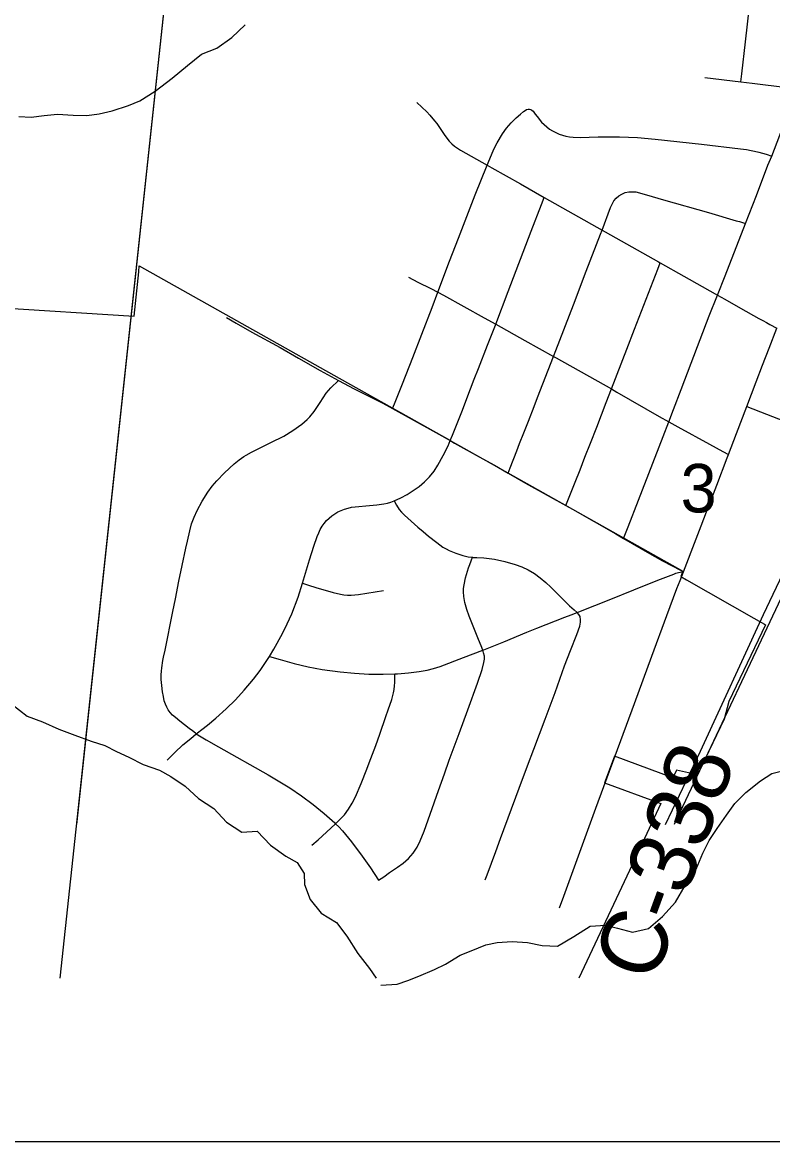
# Model space of a CAD drawing. Extents: x 0 to 34, y 0 to 22.
# Drawn here: x 7.77 to 8.418, y 17.5 to 18.466 of the extents above; entities that cross this region are included whole.
import ezdxf

# ---------------------------------------------------------------- set-up
doc = ezdxf.new("R2010")
doc.units = 0
for name, color, linetype in [('GM_X_City_Street', 7, 'Continuous'), ('GM_X_Corporation', 7, 'Continuous'), ('GM_X_County_Road', 7, 'Continuous'), ('GM_X_County_Road_Text', 7, 'Continuous'), ('GM_X_Minor_River', 7, 'Continuous'), ('GM_X_Rail_Line', 7, 'Continuous'), ('GM_X_Section_Text', 7, 'Continuous'), ('GM_X_Township_Road', 7, 'Continuous'), ('SH_Data', 7, 'Continuous')]:
    doc.layers.add(name, color=color, linetype=linetype)

msp = doc.modelspace()

# ---------------------------------------------------------------- linework, layer by layer
at = {"layer": 'GM_X_City_Street'}
for points in [[(8.39057, 18.41491), (8.39137, 18.42185), (8.39458, 18.44966), (8.39815, 18.48268)], [(8.35951, 18.41869), (8.39057, 18.41491), (8.40032, 18.41372), (8.43058, 18.41003), (8.44479, 18.4083), (8.46831, 18.40561), (8.49197, 18.4029), (8.49837, 18.40217)], [(8.28928, 18.02081), (8.29097, 18.02504), (8.29327, 18.03079), (8.30223, 18.05392), (8.32332, 18.1089), (8.32823, 18.1215), (8.33232, 18.13199), (8.33888, 18.14938), (8.34762, 18.17223), (8.36327, 18.21306), (8.37032, 18.23086), (8.37694, 18.2476), (8.39454, 18.29282), (8.40391, 18.31691), (8.41392, 18.34295), (8.41728, 18.35096), (8.42199, 18.36288), (8.42512, 18.37138), (8.42684, 18.37719), (8.42808, 18.3832), (8.42845, 18.38618), (8.42917, 18.39509), (8.43003, 18.4042), (8.43058, 18.41003)], [(8.08974, 18.13293), (8.09141, 18.13708), (8.09831, 18.15414), (8.10728, 18.17697), (8.11503, 18.19714), (8.12384, 18.2203), (8.12881, 18.23335), (8.13899, 18.26014), (8.14682, 18.27989), (8.16114, 18.31735), (8.17135, 18.34309), (8.17368, 18.34857), (8.17726, 18.35698), (8.18, 18.36239), (8.18466, 18.37017), (8.18824, 18.37504), (8.1922, 18.3796), (8.19649, 18.38389), (8.20019, 18.3872), (8.20274, 18.38927), (8.20424, 18.39032), (8.20555, 18.39105), (8.20683, 18.39136)], [(8.11083, 18.39703), (8.11929, 18.38897), (8.12202, 18.38621), (8.12599, 18.38142), (8.12786, 18.37893), (8.13477, 18.36853), (8.1387, 18.3637), (8.14091, 18.3615), (8.14329, 18.3595), (8.14847, 18.35603), (8.17135, 18.34309), (8.17561, 18.34068), (8.20011, 18.32698), (8.22077, 18.31527), (8.27069, 18.287), (8.27336, 18.28548), (8.31953, 18.25945), (8.32088, 18.2587), (8.34134, 18.24734), (8.36841, 18.23192), (8.37032, 18.23086), (8.37664, 18.22736), (8.39008, 18.21953), (8.40615, 18.21078), (8.40954, 18.20893), (8.41256, 18.20729), (8.41561, 18.20562), (8.42157, 18.20238)], [(8.20683, 18.39136), (8.20788, 18.39132), (8.20908, 18.39109), (8.21009, 18.39063), (8.21121, 18.38958), (8.21296, 18.38721), (8.21453, 18.38512), (8.2184, 18.3803), (8.22056, 18.37809), (8.2229, 18.37608), (8.22539, 18.37425), (8.22802, 18.37263), (8.23359, 18.36995), (8.2365, 18.3689), (8.23948, 18.36811), (8.24252, 18.36754), (8.24559, 18.36718), (8.25177, 18.36698), (8.26721, 18.36744), (8.28575, 18.36757), (8.30119, 18.36688), (8.31658, 18.36554), (8.35652, 18.36106), (8.39031, 18.35722), (8.39553, 18.35654), (8.39945, 18.35574), (8.40228, 18.35513), (8.40598, 18.35421), (8.41226, 18.35241), (8.41728, 18.35096)], [(8.13965, 18.10525), (8.14159, 18.11005), (8.1497, 18.13006), (8.15716, 18.15006), (8.16033, 18.15828), (8.16392, 18.16757), (8.17188, 18.18767), (8.17869, 18.20492), (8.17897, 18.20568), (8.18955, 18.23391), (8.20947, 18.28601), (8.21834, 18.30898), (8.22077, 18.31527)], [(8.18954, 18.07725), (8.19126, 18.08168), (8.19702, 18.09642), (8.19945, 18.10264), (8.20306, 18.1119), (8.20703, 18.12207), (8.21199, 18.13479), (8.21501, 18.14252), (8.22884, 18.17795), (8.23086, 18.18312), (8.24602, 18.22249), (8.25705, 18.2515), (8.26931, 18.28335), (8.27069, 18.287), (8.27808, 18.30659), (8.27934, 18.30942), (8.28083, 18.31214), (8.28277, 18.31454), (8.28515, 18.31653), (8.28781, 18.31814), (8.29068, 18.31932), (8.29371, 18.31996), (8.29681, 18.32016), (8.2999, 18.31988), (8.3089, 18.31747), (8.32381, 18.31317), (8.36264, 18.30208), (8.3865, 18.29512), (8.38948, 18.29427), (8.39454, 18.29282)], [(8.23942, 18.04914), (8.24123, 18.05363), (8.24753, 18.06927), (8.25164, 18.07987), (8.25592, 18.09089), (8.26059, 18.10295), (8.26603, 18.11696), (8.27427, 18.13823), (8.27875, 18.14983), (8.29196, 18.18405), (8.29854, 18.20139), (8.31876, 18.25324), (8.32088, 18.2587)], [(8.10356, 18.24647), (8.11163, 18.24198), (8.12269, 18.23645), (8.12881, 18.23335), (8.13371, 18.23086), (8.16886, 18.21132), (8.17897, 18.20568), (8.20406, 18.19169), (8.22884, 18.17795), (8.23115, 18.17666), (8.27875, 18.14983), (8.28342, 18.14719), (8.32004, 18.12612), (8.32823, 18.1215), (8.33619, 18.11701), (8.36348, 18.10209), (8.37503, 18.09577), (8.37976, 18.09319)]]:
    msp.add_lwpolyline(points, dxfattribs=at)
at = {"layer": 'GM_X_Corporation'}
for points in [[(6.81318, 17.77385), (6.90013, 18.71944), (7.91015, 18.64382), (7.81673, 17.77385)], [(8.81833, 17.64118), (8.84939, 17.97112), (8.84939, 18.54746), (7.91015, 18.64382), (7.80248, 17.64118)], [(7.74797, 18.22005), (7.86663, 18.21267), (7.87056, 18.25102), (7.87108, 18.25615), (8.04362, 18.15925), (8.08951, 18.13346), (8.13931, 18.1055), (8.1394, 18.10545), (8.16764, 18.0896), (8.18921, 18.07748), (8.34034, 17.99261), (8.33858, 17.98797), (8.34357, 17.98511), (8.4018, 17.95187), (8.41079, 17.94674), (8.41178, 17.94617), (8.39899, 17.91956), (8.38005, 17.87994), (8.37618, 17.86473), (8.35298, 17.81663), (8.33506, 17.82084), (8.33191, 17.81415), (8.28131, 17.83285), (8.27283, 17.80973), (8.32132, 17.79181), (8.30122, 17.74887), (8.26665, 17.67548), (8.25055, 17.64118)]]:
    msp.add_lwpolyline(points, dxfattribs=at)
at = {"layer": 'GM_X_County_Road'}
msp.add_line((8.33797, 17.98433), (8.33914, 17.98722), dxfattribs=at)
for points in [[(8.39566, 18.1346), (8.40364, 18.15602), (8.40921, 18.17033), (8.41492, 18.18512), (8.42157, 18.20238)], [(8.37976, 18.09319), (8.38668, 18.11125), (8.39566, 18.1346)], [(8.39566, 18.1346), (8.43475, 18.11949), (8.4723, 18.10454), (8.48894, 18.09803)], [(8.34095, 17.99194), (8.35185, 18.02042), (8.35613, 18.03159), (8.3608, 18.04378), (8.36535, 18.0556), (8.36963, 18.06676), (8.37864, 18.09027), (8.37976, 18.09319)], [(8.23389, 17.70192), (8.23752, 17.71191), (8.25145, 17.74986), (8.26524, 17.78789), (8.29874, 17.8783), (8.31367, 17.91922), (8.32666, 17.95421), (8.33525, 17.97759), (8.33797, 17.98433)], [(8.33914, 17.98722), (8.34004, 17.98958), (8.34095, 17.99194)]]:
    msp.add_lwpolyline(points, dxfattribs=at)
at = {"layer": 'GM_X_Minor_River'}
for points in [[(7.76709, 18.38499), (7.77767, 18.38453), (7.78903, 18.38596), (7.80039, 18.38702), (7.814, 18.38616), (7.82573, 18.38607), (7.83633, 18.38751), (7.8477, 18.39008), (7.86173, 18.39453), (7.8716, 18.39862), (7.8849, 18.40687), (7.89936, 18.41814), (7.91268, 18.42903), (7.92486, 18.4388), (7.93814, 18.44401), (7.95107, 18.4534), (7.96251, 18.46431)], [(7.76101, 17.87774), (7.77418, 17.8674), (7.78738, 17.86238), (7.80171, 17.85621), (7.81529, 17.8508), (7.82962, 17.84576), (7.84132, 17.84189), (7.8515, 17.83688), (7.86205, 17.83187), (7.87449, 17.82572), (7.88845, 17.82068), (7.89824, 17.8153), (7.91067, 17.80687), (7.92231, 17.79617), (7.93549, 17.78773), (7.94637, 17.7759), (7.95955, 17.76708), (7.97279, 17.76812), (7.98443, 17.7559), (7.9976, 17.74632), (8.00739, 17.74094), (8.01338, 17.73142), (8.01368, 17.72194), (8.0185, 17.70901), (8.02825, 17.69719), (8.04143, 17.68913), (8.05042, 17.67731), (8.05977, 17.66245), (8.06988, 17.64949), (8.07557, 17.64118)], [(8.07965, 17.63516), (8.09361, 17.63604), (8.10309, 17.639), (8.11258, 17.64273), (8.12587, 17.64869), (8.13536, 17.65317), (8.14828, 17.66104), (8.15776, 17.66476), (8.17028, 17.66997), (8.18013, 17.67179), (8.193, 17.67283), (8.20624, 17.67198), (8.21908, 17.66923), (8.23231, 17.66875), (8.24637, 17.67699), (8.26044, 17.68598), (8.27406, 17.68702), (8.28388, 17.68429), (8.29709, 17.68078), (8.31073, 17.68409), (8.32292, 17.69423), (8.33398, 17.70666), (8.34241, 17.72101), (8.35197, 17.73534), (8.35775, 17.74895), (8.36313, 17.7599), (8.37002, 17.77047), (8.37805, 17.78178), (8.38531, 17.79196), (8.39484, 17.80137), (8.4074, 17.81151), (8.41728, 17.81788), (8.43092, 17.82119)]]:
    msp.add_lwpolyline(points, dxfattribs=at)
at = {"layer": 'GM_X_Rail_Line'}
msp.add_line((8.48609, 18.09862), (8.3328, 17.77385), dxfattribs=at)
msp.add_lwpolyline([(8.32534, 17.77385), (8.35571, 17.83724), (8.4101, 17.95501), (8.56123, 18.27286), (8.65767, 18.47815), (8.8437, 18.88139), (8.84939, 18.89278)], dxfattribs=at)
at = {"layer": 'GM_X_Township_Road'}
for points in [[(7.94631, 18.21145), (7.95487, 18.20651), (7.9682, 18.19882), (7.99261, 18.18568), (8.00852, 18.17637), (8.02725, 18.16572), (8.04323, 18.15703)], [(7.92033, 17.85205), (7.91949, 17.85268), (7.91692, 17.85458), (7.91424, 17.8566), (7.90611, 17.86287), (7.90224, 17.86612), (7.89988, 17.86821), (7.8978, 17.87045), (7.89615, 17.87282), (7.89477, 17.87503), (7.89373, 17.87764), (7.89269, 17.88054), (7.89194, 17.88421), (7.89111, 17.88846), (7.89051, 17.89376), (7.88999, 17.89912), (7.89003, 17.90303), (7.8902, 17.9061), (7.89058, 17.90919), (7.89148, 17.9153), (7.89212, 17.91822), (7.89332, 17.92433), (7.90006, 17.95781), (7.90224, 17.96868), (7.90532, 17.98395), (7.90801, 17.99731), (7.91132, 18.01244), (7.91259, 18.01844), (7.91462, 18.0274), (7.91631, 18.03336), (7.91844, 18.03917), (7.92097, 18.04476), (7.9254, 18.05292), (7.93039, 18.0608), (7.9341, 18.0658), (7.93807, 18.07058), (7.94475, 18.0773), (7.95295, 18.08506), (7.95722, 18.08852), (7.96126, 18.09148), (7.96329, 18.0928), (7.96787, 18.0954), (7.98466, 18.10358), (7.99575, 18.1092), (8.00375, 18.11399), (8.01133, 18.11944), (8.01606, 18.12347), (8.01825, 18.12567), (8.02217, 18.1305), (8.02735, 18.13827), (8.03243, 18.14609), (8.03634, 18.1509), (8.04323, 18.15703)], [(8.04323, 18.15703), (8.05672, 18.14987), (8.08131, 18.13757), (8.08974, 18.13293)], [(8.08974, 18.13293), (8.12723, 18.11223), (8.13965, 18.10525)], [(8.09123, 18.05325), (8.09682, 18.05571), (8.10226, 18.05873), (8.10755, 18.06203), (8.11266, 18.06559), (8.11738, 18.06961), (8.1217, 18.07409), (8.12559, 18.07895), (8.12896, 18.08417), (8.13359, 18.09243), (8.13781, 18.10071), (8.13965, 18.10525)], [(8.13965, 18.10525), (8.14337, 18.10316), (8.1645, 18.09128), (8.17787, 18.08392), (8.18954, 18.07725)], [(8.18954, 18.07725), (8.20465, 18.06861), (8.23942, 18.04914)], [(8.01215, 17.98215), (8.01806, 18.00223), (8.02193, 18.01406), (8.02469, 18.02245), (8.02607, 18.02575), (8.02738, 18.02857), (8.02893, 18.03127), (8.03074, 18.03381), (8.03278, 18.03616), (8.03502, 18.03832), (8.03741, 18.0403), (8.03995, 18.04208), (8.04265, 18.04365), (8.04545, 18.045), (8.04835, 18.04614), (8.05133, 18.04705), (8.05437, 18.04772), (8.06055, 18.04844), (8.06676, 18.04896), (8.07606, 18.04979), (8.08223, 18.05058), (8.08529, 18.05117), (8.08829, 18.05196), (8.09123, 18.05325)], [(8.09123, 18.05325), (8.09324, 18.04941), (8.09554, 18.0458), (8.09763, 18.04335), (8.10006, 18.04076), (8.11173, 18.03048), (8.11619, 18.02668), (8.12094, 18.02276), (8.12798, 18.01721), (8.13331, 18.01327), (8.13594, 18.01167), (8.13868, 18.01027), (8.14442, 18.00802), (8.15031, 18.00617), (8.1552, 18.00502), (8.15875, 18.00453)], [(8.23942, 18.04914), (8.24502, 18.04601), (8.28266, 18.02462), (8.28928, 18.02081)], [(8.28928, 18.02081), (8.31171, 18.00791), (8.32289, 18.00151), (8.3383, 17.99335), (8.34095, 17.99194)], [(8.16765, 17.92422), (8.1663, 17.92806), (8.16398, 17.93364), (8.16292, 17.93653), (8.15809, 17.94779), (8.15584, 17.95353), (8.15391, 17.9594), (8.15232, 17.96539), (8.15123, 17.97065), (8.151, 17.9746), (8.15104, 17.97758), (8.15149, 17.98063), (8.15279, 17.98667), (8.15358, 17.98961), (8.15544, 17.99535), (8.15649, 17.99824), (8.15875, 18.00453)], [(8.15875, 18.00453), (8.15938, 18.00445), (8.16241, 18.00438), (8.16854, 18.00406), (8.17769, 18.00287), (8.18673, 18.0009), (8.19561, 17.99831), (8.20139, 17.99615), (8.20699, 17.9936), (8.2123, 17.99046), (8.21729, 17.98684), (8.22201, 17.98287), (8.2265, 17.97863), (8.23751, 17.96765), (8.24244, 17.96271), (8.24645, 17.9592), (8.24918, 17.95696)], [(8.24918, 17.95696), (8.26441, 17.96292), (8.27829, 17.96836), (8.29814, 17.97634), (8.3187, 17.98462), (8.33272, 17.99006), (8.33451, 17.9907), (8.33654, 17.99128), (8.33806, 17.99156), (8.34095, 17.99194)], [(7.98341, 17.91894), (7.98716, 17.92513), (7.99469, 17.93877), (7.99888, 17.94712), (8.00267, 17.95564), (8.00823, 17.97007), (8.01215, 17.98215)], [(8.01215, 17.98215), (8.01729, 17.98053), (8.0236, 17.97853), (8.03863, 17.97399), (8.04474, 17.97253), (8.04784, 17.97203), (8.05096, 17.97175), (8.05409, 17.97173), (8.06034, 17.97239), (8.08207, 17.97581)], [(8.16765, 17.92422), (8.16854, 17.92455), (8.18576, 17.93148), (8.20578, 17.93977), (8.21428, 17.94318), (8.23857, 17.9529), (8.24404, 17.95493), (8.24918, 17.95696)], [(8.16973, 17.72589), (8.17157, 17.7302), (8.17887, 17.7506), (8.18312, 17.76161), (8.19909, 17.80525), (8.2063, 17.82433), (8.21176, 17.83877), (8.2215, 17.86473), (8.23013, 17.88783), (8.23834, 17.91072), (8.2434, 17.92389), (8.24896, 17.93784), (8.25147, 17.94495), (8.25214, 17.94844), (8.25214, 17.95047), (8.25165, 17.95334), (8.25067, 17.95515), (8.24918, 17.95696)], [(7.92033, 17.85205), (7.92144, 17.85295), (7.92517, 17.85584), (7.93011, 17.85967), (7.93727, 17.8656), (7.94607, 17.87365), (7.95414, 17.88147), (7.96173, 17.88979), (7.96968, 17.89925), (7.97538, 17.90671), (7.9807, 17.91446), (7.98341, 17.91894)], [(7.98341, 17.91894), (7.99286, 17.91625), (8.0048, 17.91285), (8.01691, 17.91003), (8.02912, 17.90771), (8.04453, 17.90557), (8.0569, 17.90433), (8.06932, 17.90363), (8.08175, 17.90352), (8.09188, 17.90386)], [(8.07774, 17.72568), (8.08213, 17.72872), (8.08714, 17.73221), (8.094, 17.73697), (8.09888, 17.74036), (8.10356, 17.74438), (8.10568, 17.74663), (8.10763, 17.74904), (8.1094, 17.75159), (8.11098, 17.75424), (8.11357, 17.75963), (8.11702, 17.76816), (8.12211, 17.78272), (8.1293, 17.8031), (8.13453, 17.81763), (8.13878, 17.82921), (8.14732, 17.85236), (8.15478, 17.87265), (8.16319, 17.89587), (8.16713, 17.90758), (8.16873, 17.91355), (8.16916, 17.91661), (8.16902, 17.91908), (8.16843, 17.92198), (8.16765, 17.92422)], [(8.09188, 17.90386), (8.09418, 17.90394), (8.10348, 17.90466), (8.11273, 17.90586), (8.11977, 17.90718), (8.1252, 17.9085), (8.13079, 17.91032), (8.1511, 17.91803), (8.16765, 17.92422)], [(8.04064, 17.77451), (8.04482, 17.77875), (8.04825, 17.78223), (8.05176, 17.78696), (8.05494, 17.79224), (8.05771, 17.79775), (8.06256, 17.8091), (8.06748, 17.82169), (8.06952, 17.82714), (8.07522, 17.84207), (8.07887, 17.85164), (8.08411, 17.86694), (8.08605, 17.87281), (8.08904, 17.88157), (8.09066, 17.88748), (8.09124, 17.89049), (8.09157, 17.89352), (8.09166, 17.89638), (8.09188, 17.90386)], [(7.89516, 17.82926), (7.90164, 17.83592), (7.90878, 17.84243), (7.91552, 17.84818), (7.92033, 17.85205)], [(7.92033, 17.85205), (7.92876, 17.84697), (7.93938, 17.84093), (7.98248, 17.8168), (8.00093, 17.80545), (8.01121, 17.79855), (8.02116, 17.79118), (8.03077, 17.78337), (8.04002, 17.77515), (8.04064, 17.77451)], [(8.02021, 17.75584), (8.02546, 17.76061), (8.0364, 17.77054), (8.04064, 17.77451)], [(8.04064, 17.77451), (8.04335, 17.77167), (8.04643, 17.76844), (8.05421, 17.75881), (8.06358, 17.74649), (8.07072, 17.73636), (8.07774, 17.72568)]]:
    msp.add_lwpolyline(points, dxfattribs=at)
at = {"layer": 'SH_Data'}
msp.add_line((2, 17.5), (9, 17.5), dxfattribs=at)

# ---------------------------------------------------------------- texts
at = {"layer": 'GM_X_County_Road_Text'}
msp.add_text('C-338', height=0.056818, rotation=69.92384, dxfattribs=at).set_placement((8.31546, 17.63547))
at = {"layer": 'GM_X_Section_Text'}
msp.add_text('3', height=0.04186, rotation=0.00001, dxfattribs=at).set_placement((8.33845, 18.04326))

doc.saveas('drawing.dxf')
